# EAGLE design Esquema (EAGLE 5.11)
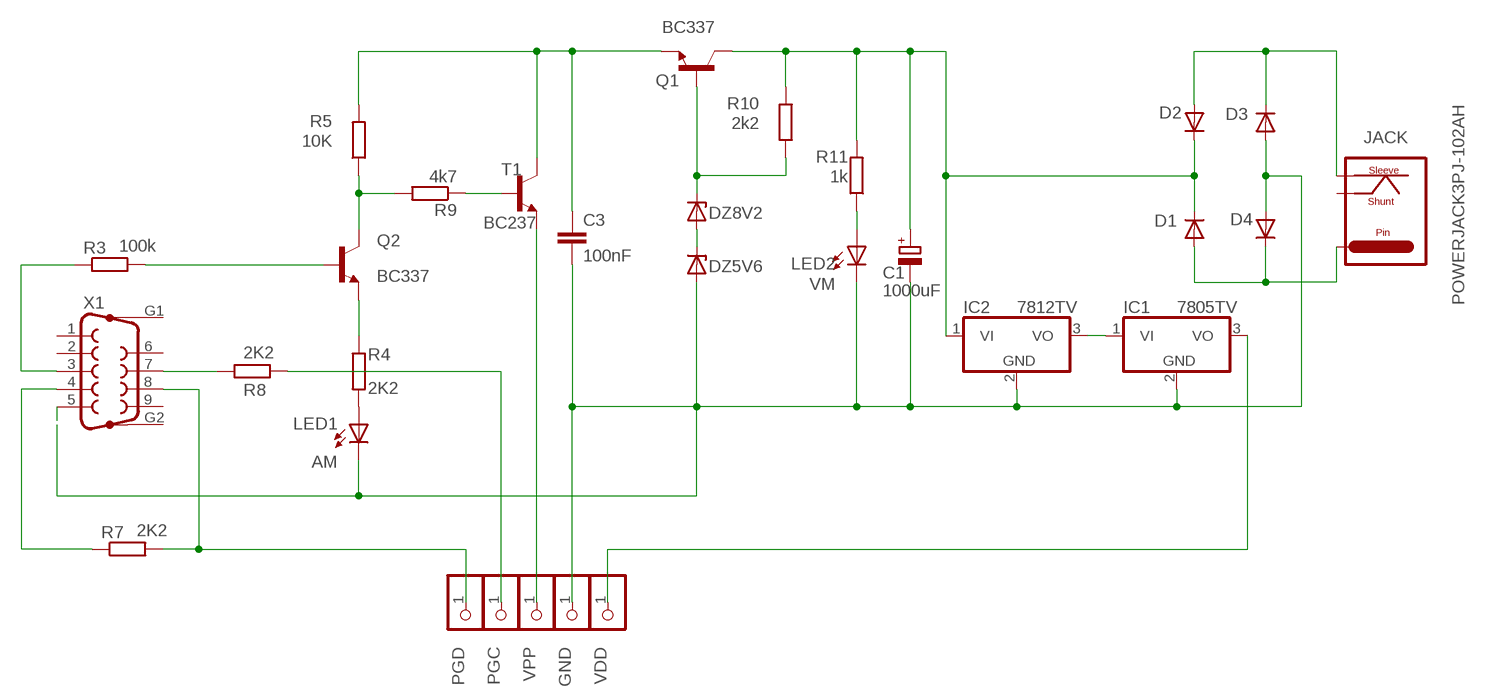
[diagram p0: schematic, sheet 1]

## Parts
C1  1000uF  CPOL-EUE5-10.5  [E5-10,5]
C3  100nF  C-EU025-025X050  [C025-025X050]
D1  1N4004  [DO41-10]
D2  1N4004  [DO41-10]
D3  1N4004  [DO41-10]
D4  1N4004  [DO41-10]
DZ5V6  BZX90  [DO34Z7]
DZ8V2  BZX90  [DO34Z7]
GND  PINHD-1X1  [1X01]
IC1  7805TV  [TO220V]
IC2  7812TV  [TO220V]
JACK  POWERJACK3PJ-102AH  [PJ-102AH]
LED1  AM  LED5MM  [LED5MM]
LED2  VM  LED5MM  [LED5MM]
PGC  PINHD-1X1  [1X01]
PGD  PINHD-1X1  [1X01]
Q1  BC337  [TO92]
Q2  BC337  [TO92]
R3  100k  R-EU_0207/10  [0207/10]
R4  2K2  R-EU_0207/10  [0207/10]
R5  10K  R-EU_0207/10  [0207/10]
R7  2K2  R-EU_0207/10  [0207/10]
R8  2K2  R-EU_0207/10  [0207/10]
R9  4k7  R-EU_0207/10  [0207/10]
R10  2k2  R-EU_0207/10  [0207/10]
R11  1k  R-EU_0207/10  [0207/10]
T1  BC237  [TO92]
VDD  PINHD-1X1  [1X01]
VPP  PINHD-1X1  [1X01]
X1  F09HP  [F09HP]

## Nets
N$1: T1.1(E) VPP.1
N$2: R7.1 X1.4
N$3: R8.2 X1.7
N$5: R3.1 X1.3
N$6: Q2.2(B) R3.2
N$7: C3.1 Q1.1(E) R5.2 T1.3(C)
N$8: DZ8V2.C Q1.2(B) R10.1
N$9: LED1.A R4.2
N$10: C1.+ D1.C D2.C IC2.1(VI) Q1.3(C) R10.2 R11.2
N$11: D2.A D3.C JACK.SLEEVE
N$12: C1.- C3.2 D3.A D4.A DZ5V6.A GND.1 IC1.2(GND) IC2.2(GND) LED1.K(C) LED2.K(C) X1.5
N$13: R9.1 T1.2(B)
N$14: DZ5V6.C DZ8V2.A
N$15: Q2.3(C) R5.1 R9.2
N$17: LED2.A R11.1
N$19: Q2.1(E) R4.1
N$20: D1.A D4.C JACK.CENTER(PIN)
N$21: IC1.3(VO) VDD.1
N$22: IC1.1(VI) IC2.3(VO)
N$23: PGC.1 R8.1
N$26: PGD.1 R7.2 X1.8
Unconnected: JACK.SWITCH(SHUNT) X1.1 X1.2 X1.6 X1.9 X1.G1 X1.G2

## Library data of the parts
C1 = rcl:CPOL-EU: POLARIZED CAPACITOR, European symbol
C3 = rcl:C-EU: CAPACITOR, European symbol
D1-D4 = diode:1N4004: DIODE
DZ5V6 DZ8V2 = diode:BZX90: Z DIODE
GND PGC PGD VDD VPP = pinhead:PINHD-1X1: PIN HEADER
IC1 IC2 = linear:78*: Positive VOLTAGE REGULATOR Source: http://cache.national.com/ds/LM/LM78L05.pdf http://www.fairchildsemi.com/ds/LM/LM7805.pdf
JACK = ads4:POWERJACK3: Pin-Sleeve-Shunt Power Jack
LED1 LED2 = led:LED: LED
Q1 Q2 = transistor:BC337: NPN TRANSISTOR
R3-R5 R7-R11 = rcl:R-EU_: RESISTOR, European symbol
T1 = transistor:BC237: NPN TRANSISTOR
X1 = con-subd:F09HP: SUB-D

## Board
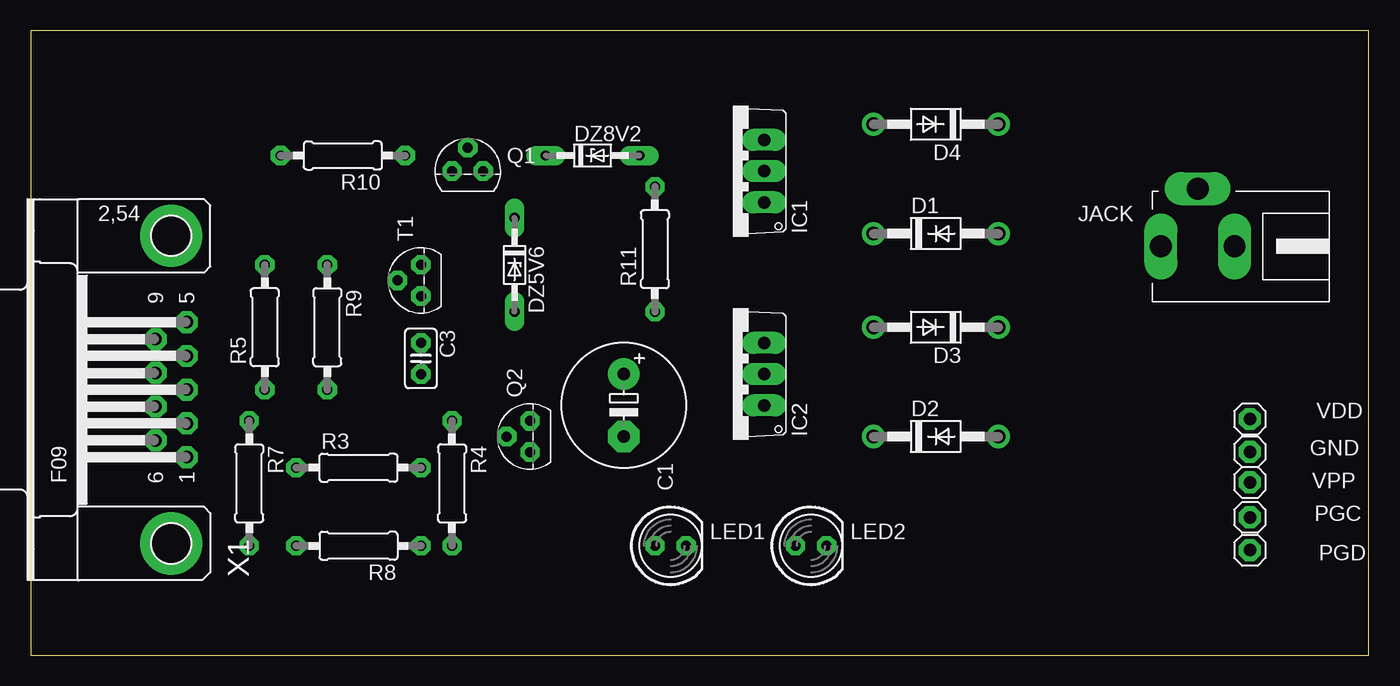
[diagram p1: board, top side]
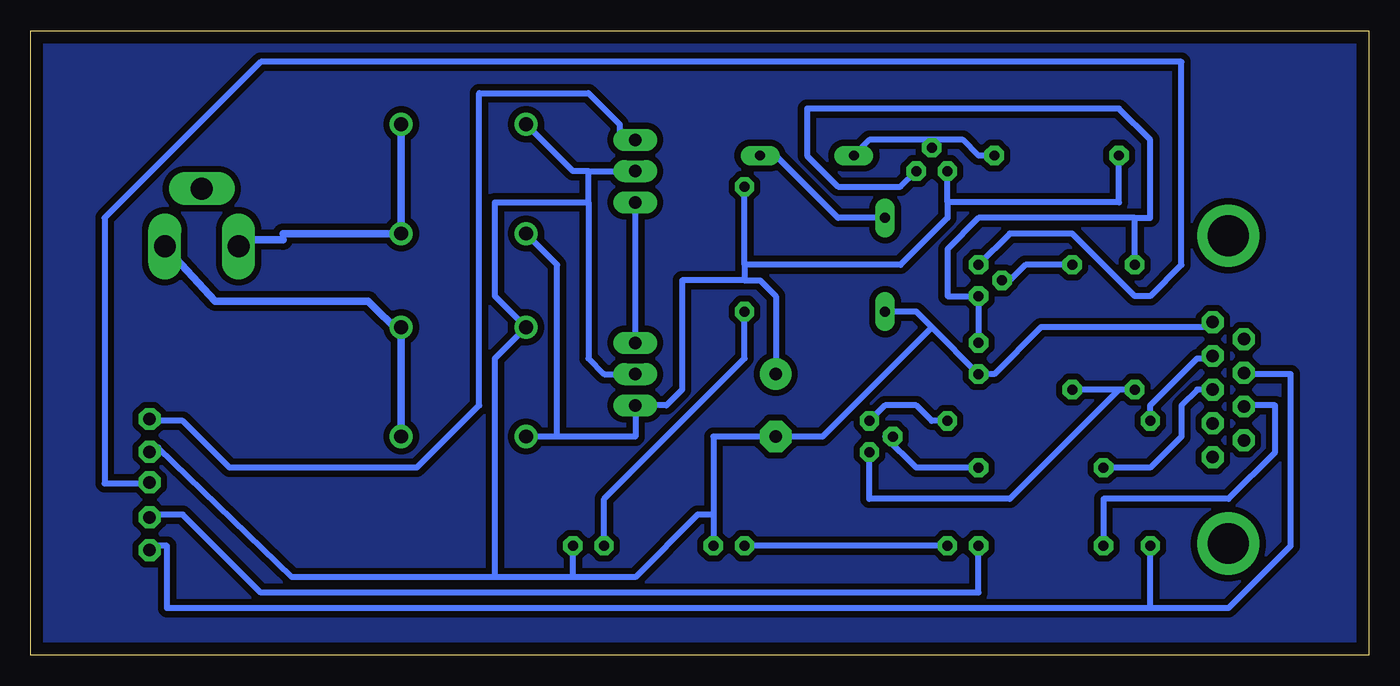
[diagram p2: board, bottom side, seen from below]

Size 108.89 x 50.79 mm. Coordinates in mm from the lower left corner, seen from the top.
Outline: 0,0 108.89,0 108.89,50.79 0,50.79 0,0
Copper layers (1*16): Top 0.035mm / dielectric 1.5mm / Bottom 0.035mm
Design rules "default *": minimum track width 20mil, minimum drill 24mil, track to track 20mil, track to pad 20mil, pad to pad 20mil, via to via 20mil, smd to smd 8mil, copper to edge 40mil, drill to drill 8mil, minimum pad ring 15mil, minimum via ring 18mil, stop-mask expansion 4mil, vias tented up to drill 0mil, thermal gap 10mil

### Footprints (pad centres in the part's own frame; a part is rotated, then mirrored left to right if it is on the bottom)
E5-10,5 = drill 1.016 pad 2.54 round: + -2.54,0 | drill 1.016 pad 2.54 octagon: - 2.54,0
C025-025X050 = drill 0.813 octagon: 1 -1.27,0; 2 1.27,0
DO41-10 = drill 1.118 round: A 5.08,0; C -5.08,0
DO34Z7 = drill 0.813 long: A 3.81,0; C -3.81,0
1X01 = drill 1.016 octagon: 1 0,0
TO220V = drill 1.016 long: 1 -2.54,-2.54; 2 0,-2.54; 3 2.54,-2.54
PJ-102AH = drill 1.778 long: CENTER -6,0; SLEEVE 0,0; SWITCH -3,4.7
LED5MM = drill 0.813 octagon: A -1.27,0; K 1.27,0
TO92 = drill 0.813 octagon: 1 1.27,0; 2 0,1.905; 3 -1.27,0
0207/10 = drill 0.813 octagon: 1 -5.08,0; 2 5.08,0
F09HP = drill 1.016 octagon: 1 -5.486,-1.27; 2 -2.743,-1.27; 3 0,-1.27; 4 2.743,-1.27; 5 5.486,-1.27; 6 -4.115,1.27; 7 -1.372,1.27; 8 1.372,1.27; 9 4.115,1.27 | drill 3.302 pad 5.08 round: G1 -12.522,0; G2 12.522,0

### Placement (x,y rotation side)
C1  48.26,20.32 270 top
C3  31.75,24.13 270 top
D1  73.66,34.29 0 top
D2  73.66,17.78 0 top
D3  73.66,26.67 180 top
D4  73.66,43.18 180 top
DZ5V6  39.37,31.75 270 top
DZ8V2  45.72,40.64 0 top
GND  99.21,16.54 0 top
IC1  57.15,39.37 90 top
IC2  57.15,22.86 90 top
JACK  97.97,33.25 0 top
LED1  52.07,8.89 0 top
LED2  63.5,8.89 0 top
PGC  99.21,11.2 0 top
PGD  99.21,8.53 0 top
Q1  35.56,39.37 0 top
Q2  40.64,17.78 90 top
R3  26.67,15.24 0 top
R4  34.29,13.97 270 top
R5  19.05,26.67 90 top
R7  17.78,13.97 270 top
R8  26.67,8.89 180 top
R9  24.13,26.67 270 top
R10  25.4,40.64 180 top
R11  50.8,33.02 90 top
T1  31.75,30.48 90 top
VDD  99.21,19.2 0 top
VPP  99.21,14.05 0 top
X1  11.43,21.59 90 top

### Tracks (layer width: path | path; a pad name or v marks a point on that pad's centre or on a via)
N$1
  Bottom 0.508: T1.1 29.21,34.29 24.13,34.29 19.05,29.21 17.78,29.21 15.24,31.75 15.24,48.26 90.17,48.26 102.87,35.56 102.87,13.97 99.06,13.97 VPP.1
N$2
  Bottom 0.508: R7.1 17.78,20.32 13.97,24.13 12.7,24.13 X1.4
N$3
  Bottom 0.508: R8.2 21.59,12.7 11.43,12.7 7.62,16.51 7.62,20.32 10.16,20.32 X1.7
N$5
  Bottom 0.508: R3.1 17.78,15.24 15.24,17.78 15.24,20.32 13.97,21.59 X1.3
N$6
  Bottom 0.508: R3.2 36.83,15.24 39.37,17.78 Q2.2
N$7
  Bottom 0.508: C3.1 T1.3 34.29,29.21 34.29,33.02 31.75,35.56 19.05,35.56 | R5.2 19.05,35.56 | Q1.1 38.1,38.1 43.18,38.1 45.72,40.64 45.72,44.45 20.32,44.45 17.78,41.91 17.78,35.56 19.05,35.56
N$8
  Bottom 0.508: R10.1 31.75,40.64 33.02,41.91 35.56,41.91 | DZ8V2.C 40.64,41.91 35.56,41.91 | 35.56,41.91 Q1.2
N$9
  Bottom 0.508: R4.2 LED1.A
N$10
  Bottom 0.508: 66.04,17.78 D2.C | 66.04,17.78 59.69,17.78 IC2.1 57.15,20.32 55.88,21.59 55.88,30.48 50.8,30.48 | D1.C 66.04,31.75 66.04,17.78 | 50.8,31.75 50.8,30.48 | 50.8,31.75 R11.2 | 50.8,30.48 49.53,30.48 48.26,29.21 C1.+ | 34.29,36.83 34.29,35.56 38.1,31.75 50.8,31.75 | 34.29,36.83 Q1.3 | R10.2 20.32,36.83 34.29,36.83
N$11
  Bottom 0.305: 78.74,26.14 D3.C
  Bottom 0.61: D2.A 78.74,26.14 81.43,28.8 93.88,28.8 JACK.SLEEVE
N$12
  Bottom 0.508: 35.56,26.67 36.83,27.94 DZ5V6.A | 35.56,26.67 C3.2 30.48,22.86 26.67,26.67 12.7,26.67 X1.5 | IC2.2 62.23,22.86 63.5,24.13 63.5,36.83 | 63.5,36.83 63.5,39.37 | 63.5,39.37 IC1.2 | 63.5,36.83 71.12,36.83 71.12,29.21 D3.A 71.12,24.13 71.12,6.35 | D4.A 64.77,39.37 63.5,39.37 | 53.34,11.43 53.34,17.78 C1.- 44.45,17.78 35.56,26.67 | 53.34,11.43 LED1.K | 64.77,6.35 LED2.K | 64.77,6.35 59.69,6.35 54.61,11.43 53.34,11.43 | 64.77,6.35 71.12,6.35 | 71.12,6.35 87.63,6.35 98.5,16.87 99.06,16.51 GND.1
N$13
  Bottom 0.508: R9.1 27.94,31.75 29.21,30.48 T1.2
N$14
  Bottom 0.508: DZ5V6.C 43.18,35.56 48.26,40.64 DZ8V2.A
N$15
  Bottom 0.508: 20.32,21.59 R9.2 | R5.1 20.32,21.59 | Q2.3 40.64,12.7 29.21,12.7 20.32,21.59
N$17
  Bottom 0.508: R11.1 50.8,24.13 62.23,12.7 LED2.A
N$18
  pour Bottom (isolate 0.406): -0.18,50.85 108.99,50.85 108.99,0.18 -0.18,0.18
N$19
  Bottom 0.508: R4.1 35.56,19.05 36.83,20.32 39.37,20.32 Q2.1
N$20
  Bottom 0.305: 88.37,34.29 88.37,33.78 | 91.97,33.78 JACK.CENTER
  Bottom 0.61: D4.C D1.A 88.37,34.29 | 88.37,33.78 91.97,33.78
N$21
  Bottom 0.508: IC1.3 60.96,41.91 60.96,43.18 63.5,45.72 72.39,45.72 72.39,20.32 77.47,15.24 92.71,15.24 96.52,19.05 99.06,19.05 VDD.1
N$22
  Bottom 0.508: IC2.3 IC1.1
N$23
  Bottom 0.508: R8.1 31.75,5.08 90.17,5.08 96.52,11.43 99.06,11.43 PGC.1
N$26
  Bottom 0.508: 17.78,3.81 R7.2 | 17.78,3.81 11.43,3.81 6.35,8.89 6.35,22.86 10.16,22.86 X1.8 | 17.78,3.81 97.79,3.81 97.79,8.89 99.06,8.89 PGD.1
